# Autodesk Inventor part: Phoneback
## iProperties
Shininess: 64.0
Length Units: 11269
Angle Units: 11279
Time Units: 11290
Mass Units: 11283
Length Display Precision: 3
Angle Display Precision: 2
Compacted: True
Part Number: Phoneback
Document SubType Name: Modeling
Created: 2002-12
Designer: deepak
Density: 0.0
Volumn: 0.0
Area: 0.0
PropertySet Name: Model Information
Control State: 0
Master: False
Checked Out: False
Author: deepak
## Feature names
1. Loft1
2. Split1
3. Shell1
